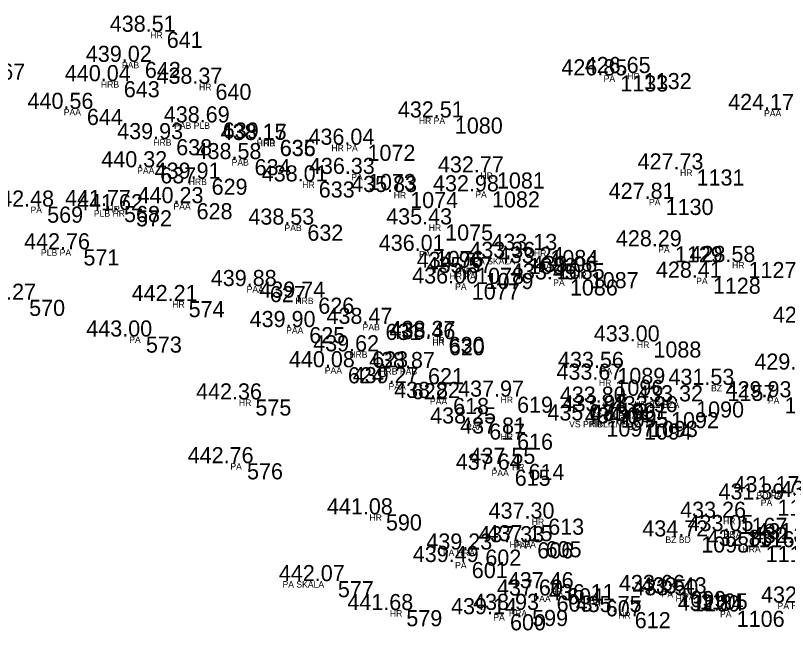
# Model space of a CAD drawing. Extents: x -639390 to -639075, y -1138747 to -1138358.
# Drawn here: x -639130.26 to -639094.29, y -1138725.69 to -1138697.05 of the extents above; entities that cross this region are included whole.
import ezdxf

# ---------------------------------------------------------------- set-up
doc = ezdxf.new("R2010")
doc.units = 0
for name, color, linetype in [('Vrstva 11', 7, 'Continuous'), ('Vrstva 12', 7, 'Continuous'), ('Vrstva 13', 7, 'Continuous'), ('Vrstva 57', 7, 'Continuous')]:
    doc.layers.add(name, color=color, linetype=linetype)

msp = doc.modelspace()

# ---------------------------------------------------------------- linework, layer by layer
at = {"layer": 'Vrstva 11'}
for p, q in [((-639123.49, -1138697.81), (-639123.49, -1138697.81)), ((-639124.51, -1138699.21), (-639124.51, -1138699.21)), ((-639102.36, -1138699.84), (-639102.36, -1138699.84)), ((-639101.27, -1138699.73), (-639101.27, -1138699.73)), ((-639125.49, -1138700.11), (-639125.49, -1138700.11)), ((-639121.22, -1138700.23), (-639121.22, -1138700.23)), ((-639127.21, -1138701.4), (-639127.21, -1138701.4)), ((-639094.59, -1138701.45), (-639094.59, -1138701.45)), ((-639110.07, -1138701.8), (-639110.07, -1138701.8)), ((-639120.88, -1138702.03), (-639120.88, -1138702.03)), ((-639123.05, -1138702.81), (-639123.05, -1138702.81)), ((-639118.23, -1138702.84), (-639118.23, -1138702.84)), ((-639118.22, -1138702.85), (-639118.22, -1138702.85)), ((-639114.14, -1138703.07), (-639114.14, -1138703.07)), ((-639119.4, -1138703.74), (-639119.4, -1138703.74)), ((-639123.79, -1138704.12), (-639123.79, -1138704.12)), ((-639108.11, -1138704.36), (-639108.11, -1138704.36)), ((-639098.81, -1138704.22), (-639098.81, -1138704.22)), ((-639121.4, -1138704.65), (-639121.4, -1138704.65)), ((-639114.12, -1138704.43), (-639114.12, -1138704.43)), ((-639116.41, -1138704.78), (-639116.41, -1138704.78)), ((-639112.15, -1138705.27), (-639112.15, -1138705.27)), ((-639108.34, -1138705.24), (-639108.34, -1138705.24)), ((-639122.1, -1138705.79), (-639122.1, -1138705.79)), ((-639100.25, -1138705.59), (-639100.25, -1138705.59)), ((-639129.06, -1138705.95), (-639129.06, -1138705.95)), ((-639125.48, -1138705.92), (-639125.48, -1138705.92)), ((-639124.92, -1138706.12), (-639124.92, -1138706.12)), ((-639116.94, -1138706.79), (-639116.94, -1138706.79)), ((-639110.52, -1138706.78), (-639110.52, -1138706.78)), ((-639127.37, -1138707.94), (-639127.37, -1138707.94)), ((-639105.62, -1138707.97), (-639105.62, -1138707.97)), ((-639099.82, -1138707.8), (-639099.82, -1138707.8)), ((-639110.96, -1138708.01), (-639110.96, -1138708.01)), ((-639106.63, -1138708.34), (-639106.63, -1138708.34)), ((-639105.32, -1138708.58), (-639105.32, -1138708.58)), ((-639096.39, -1138708.53), (-639096.39, -1138708.53)), ((-639109.08, -1138708.8), (-639109.08, -1138708.8)), ((-639108.64, -1138709.04), (-639108.64, -1138709.04)), ((-639103.74, -1138709), (-639103.74, -1138709)), ((-639104.71, -1138709.34), (-639104.71, -1138709.34)), ((-639098.05, -1138709.26), (-639098.05, -1138709.26)), ((-639118.69, -1138709.65), (-639118.69, -1138709.65)), ((-639109.28, -1138709.53), (-639109.28, -1138709.53)), ((-639129.9, -1138710.29), (-639129.9, -1138710.29)), ((-639122.47, -1138710.35), (-639122.47, -1138710.35)), ((-639116.43, -1138710.19), (-639116.43, -1138710.19)), ((-639116.85, -1138711.56), (-639116.85, -1138711.56)), ((-639113.3, -1138711.41), (-639113.3, -1138711.41)), ((-639124.46, -1138712), (-639124.46, -1138712)), ((-639110.36, -1138712.02), (-639110.36, -1138712.02)), ((-639110.35, -1138712.12), (-639110.35, -1138712.12)), ((-639100.82, -1138712.23), (-639100.82, -1138712.23)), ((-639113.92, -1138712.69), (-639113.92, -1138712.69)), ((-639115.05, -1138713.43), (-639115.05, -1138713.43)), ((-639111.32, -1138713.47), (-639111.32, -1138713.47)), ((-639102.5, -1138713.46), (-639102.5, -1138713.46)), ((-639102.59, -1138714.01), (-639102.59, -1138714.01)), ((-639112.08, -1138714.17), (-639112.08, -1138714.17)), ((-639097.37, -1138714.25), (-639097.37, -1138714.25)), ((-639107.17, -1138714.8), (-639107.17, -1138714.8)), ((-639119.36, -1138714.93), (-639119.36, -1138714.93)), ((-639110.15, -1138714.86), (-639110.15, -1138714.86)), ((-639102.4, -1138715.08), (-639102.4, -1138715.08)), ((-639098.83, -1138715.02), (-639098.83, -1138715.02)), ((-639094.71, -1138714.83), (-639094.71, -1138714.83)), ((-639102.35, -1138715.49), (-639102.35, -1138715.49)), ((-639100, -1138715.52), (-639100, -1138715.52)), ((-639108.47, -1138716.05), (-639108.47, -1138716.05)), ((-639103.01, -1138715.91), (-639103.01, -1138715.91)), ((-639101.26, -1138716.05), (-639101.26, -1138716.05)), ((-639100.98, -1138715.93), (-639100.98, -1138715.93)), ((-639107.17, -1138716.52), (-639107.17, -1138716.52)), ((-639119.75, -1138717.9), (-639119.75, -1138717.9)), ((-639106.64, -1138717.93), (-639106.64, -1138717.93)), ((-639107.28, -1138718.2), (-639107.28, -1138718.2)), ((-639094.34, -1138719.25), (-639094.34, -1138719.25)), ((-639095.04, -1138719.59), (-639095.04, -1138719.59)), ((-639113.28, -1138720.28), (-639113.28, -1138720.28)), ((-639105.72, -1138720.48), (-639105.72, -1138720.48)), ((-639096.81, -1138720.44), (-639096.81, -1138720.44)), ((-639096.48, -1138721.06), (-639096.48, -1138721.06)), ((-639106.23, -1138721.58), (-639106.23, -1138721.58)), ((-639105.84, -1138721.53), (-639105.84, -1138721.53)), ((-639098.59, -1138721.31), (-639098.59, -1138721.31)), ((-639108.65, -1138721.92), (-639108.65, -1138721.92)), ((-639095.59, -1138721.75), (-639095.59, -1138721.75)), ((-639109.28, -1138722.5), (-639109.28, -1138722.5)), ((-639115.52, -1138723.39), (-639115.52, -1138723.39)), ((-639104.84, -1138723.72), (-639104.84, -1138723.72)), ((-639105.33, -1138724.06), (-639105.33, -1138724.06)), ((-639099.66, -1138723.85), (-639099.66, -1138723.85)), ((-639099.02, -1138724.05), (-639099.02, -1138724.05)), ((-639098.66, -1138723.96), (-639098.66, -1138723.96)), ((-639103.04, -1138724.28), (-639103.04, -1138724.28)), ((-639112.33, -1138724.74), (-639112.33, -1138724.74)), ((-639106.47, -1138724.73), (-639106.47, -1138724.73)), ((-639101.69, -1138724.83), (-639101.69, -1138724.83)), ((-639096.94, -1138724.77), (-639096.94, -1138724.77)), ((-639107.5, -1138724.93), (-639107.5, -1138724.93))]:
    msp.add_line(p, q, dxfattribs=at)

# ---------------------------------------------------------------- texts
at = {"layer": 'Vrstva 12'}
for s, p in [('438.51 ', (-639125.865, -1138697.81)), ('439.02 ', (-639126.979, -1138699.21)), ('426.65 ', (-639103.74, -1138699.73)), ('426.85 ', (-639104.83, -1138699.84)), ('440.04 ', (-639127.959, -1138700.11)), ('438.37 ', (-639123.689, -1138700.23)), ('440.56 ', (-639129.696, -1138701.4)), ('424.17 ', (-639097.059, -1138701.45)), ('432.51 ', (-639112.445, -1138701.8)), ('438.69 ', (-639123.349, -1138702.03)), ('439.93 ', (-639125.519, -1138702.81)), ('438.15 ', (-639120.7, -1138702.84)), ('438.17 ', (-639120.689, -1138702.85)), ('436.04 ', (-639116.609, -1138703.07)), ('438.58 ', (-639121.869, -1138703.74)), ('440.32 ', (-639126.259, -1138704.12)), ('432.77 ', (-639110.579, -1138704.36)), ('427.73 ', (-639101.279, -1138704.22)), ('439.91 ', (-639123.775, -1138704.65)), ('438.01 ', (-639118.785, -1138704.78)), ('436.33 ', (-639116.589, -1138704.43)), ('435.83 ', (-639114.619, -1138705.27)), ('432.98 ', (-639110.809, -1138705.24)), ('440.23 ', (-639124.569, -1138705.79)), ('427.81 ', (-639102.625, -1138705.59)), ('442.48 ', (-639131.529, -1138705.95)), ('441.77 ', (-639127.949, -1138705.92)), ('441.62 ', (-639127.389, -1138706.12)), ('438.53 ', (-639119.409, -1138706.79)), ('435.43 ', (-639112.989, -1138706.78)), ('442.76 ', (-639129.856, -1138707.94)), ('436.01 ', (-639113.335, -1138708.01)), ('433.13 ', (-639108.089, -1138707.97)), ('428.29 ', (-639102.289, -1138707.8)), ('433.36 ', (-639109.116, -1138708.34)), ('433.24 ', (-639107.789, -1138708.58)), ('428.58 ', (-639098.859, -1138708.53)), ('434.96 ', (-639111.566, -1138708.8)), ('435.57 ', (-639111.109, -1138709.04)), ('433.06 ', (-639106.226, -1138709)), ('433.45 ', (-639107.18, -1138709.34)), ('428.41 ', (-639100.425, -1138709.26)), ('439.88 ', (-639121.159, -1138709.65)), ('436.00 ', (-639111.779, -1138709.53)), ('445.27 ', (-639132.369, -1138710.29)), ('442.21 ', (-639124.845, -1138710.35)), ('439.74 ', (-639118.899, -1138710.19)), ('439.90 ', (-639119.349, -1138711.56)), ('438.47 ', (-639115.769, -1138711.41)), ('427.94 ', (-639094.979, -1138711.36)), ('443.00 ', (-639126.959, -1138712)), ('438.46 ', (-639112.836, -1138712.12)), ('438.37 ', (-639112.829, -1138712.02)), ('433.00 ', (-639103.319, -1138712.23)), ('439.62 ', (-639116.389, -1138712.69)), ('440.08 ', (-639117.519, -1138713.43)), ('438.87 ', (-639113.789, -1138713.47)), ('433.56 ', (-639104.986, -1138713.46)), ('429.50 ', (-639095.839, -1138713.54)), ('433.67 ', (-639105.059, -1138714.01)), ('439.27 ', (-639114.549, -1138714.17)), ('431.53 ', (-639099.839, -1138714.25)), ('437.97 ', (-639109.639, -1138714.8)), ('429.93 ', (-639097.179, -1138714.83)), ('442.36 ', (-639121.846, -1138714.93)), ('438.82 ', (-639112.619, -1138714.86)), ('433.80 ', (-639104.899, -1138715.08)), ('433.32 ', (-639101.299, -1138715.02)), ('433.98 ', (-639104.819, -1138715.49)), ('433.96 ', (-639102.486, -1138715.52)), ('435.07 ', (-639105.479, -1138715.91)), ('433.96 ', (-639103.466, -1138715.93)), ('438.25 ', (-639110.94, -1138716.05)), ('434.04 ', (-639103.729, -1138716.05)), ('437.81 ', (-639109.545, -1138716.52)), ('442.76 ', (-639122.236, -1138717.9)), ('437.55 ', (-639109.11, -1138717.93)), ('437.64 ', (-639109.749, -1138718.2)), ('431.17 ', (-639096.809, -1138719.25)), ('431.23 ', (-639094.629, -1138719.47)), ('431.39 ', (-639097.509, -1138719.59)), ('441.08 ', (-639115.749, -1138720.28)), ('437.30 ', (-639108.219, -1138720.48)), ('433.26 ', (-639099.296, -1138720.44)), ('434.72 ', (-639101.059, -1138721.31)), ('433.05 ', (-639098.95, -1138721.06)), ('437.33 ', (-639108.699, -1138721.58)), ('437.15 ', (-639108.31, -1138721.53)), ('432.38 ', (-639095.959, -1138721.62)), ('431.79 ', (-639095.749, -1138721.44)), ('439.23 ', (-639111.119, -1138721.92)), ('432.83 ', (-639098.059, -1138721.75)), ('439.49 ', (-639111.749, -1138722.5)), ('442.07 ', (-639117.989, -1138723.39)), ('437.46 ', (-639107.326, -1138723.72)), ('437.60 ', (-639107.829, -1138724.06)), ('433.66 ', (-639102.146, -1138723.85)), ('433.50 ', (-639101.519, -1138724.05)), ('433.43 ', (-639101.129, -1138723.96)), ('436.11 ', (-639105.415, -1138724.28)), ('432.47 ', (-639095.529, -1138724.39)), ('441.68 ', (-639114.799, -1138724.74)), ('438.93 ', (-639108.939, -1138724.73)), ('435.75 ', (-639104.16, -1138724.83)), ('432.84 ', (-639099.409, -1138724.77)), ('439.14 ', (-639109.969, -1138724.93))]:
    msp.add_text(s, height=0.75, dxfattribs=at).set_placement(p)
at = {"layer": 'Vrstva 13'}
for s, p in [(' 641', (-639123.49, -1138698.56)), (' 567', (-639131.76, -1138700.04)), (' 642', (-639124.51, -1138699.96)), (' 1133', (-639102.36, -1138700.59)), (' 1132', (-639101.27, -1138700.48)), (' 643', (-639125.49, -1138700.86)), (' 640', (-639121.22, -1138700.98)), (' 644', (-639127.21, -1138702.15)), (' 1080', (-639110.07, -1138702.55)), (' 639', (-639120.88, -1138702.78)), (' 638', (-639123.05, -1138703.56)), (' 635', (-639118.23, -1138703.59)), (' 636', (-639118.22, -1138703.6)), (' 1072', (-639114.14, -1138703.82)), (' 634', (-639119.4, -1138704.49)), (' 637', (-639123.79, -1138704.87)), (' 1081', (-639108.11, -1138705.11)), (' 1131', (-639098.81, -1138704.97)), (' 629', (-639121.4, -1138705.4)), (' 1073', (-639114.12, -1138705.18)), (' 633', (-639116.41, -1138705.53)), (' 1074', (-639112.15, -1138706.02)), (' 1082', (-639108.34, -1138705.99)), (' 628', (-639122.1, -1138706.54)), (' 1130', (-639100.25, -1138706.34)), (' 569', (-639129.06, -1138706.7)), (' 568', (-639125.48, -1138706.67)), (' 572', (-639124.92, -1138706.87)), (' 632', (-639116.94, -1138707.54)), (' 1075', (-639110.52, -1138707.53)), (' 571', (-639127.37, -1138708.69)), (' 1084', (-639105.62, -1138708.72)), (' 1129', (-639099.82, -1138708.55)), (' 1076', (-639110.96, -1138708.76)), (' 1083', (-639106.63, -1138709.09)), (' 1085', (-639105.32, -1138709.33)), (' 1127', (-639096.39, -1138709.28)), (' 1078', (-639109.08, -1138709.55)), (' 1079', (-639108.64, -1138709.79)), (' 1087', (-639103.74, -1138709.75)), (' 1086', (-639104.71, -1138710.09)), (' 1128', (-639098.05, -1138710.01)), (' 627', (-639118.69, -1138710.4)), (' 1077', (-639109.28, -1138710.28)), (' 570', (-639129.9, -1138711.04)), (' 574', (-639122.47, -1138711.1)), (' 626', (-639116.43, -1138710.94)), (' 625', (-639116.85, -1138712.31)), (' 631', (-639113.3, -1138712.16)), (' 573', (-639124.46, -1138712.75)), (' 630', (-639110.36, -1138712.77)), (' 620', (-639110.35, -1138712.87)), (' 1088', (-639100.82, -1138712.98)), (' 623', (-639113.92, -1138713.44)), (' 624', (-639115.05, -1138714.18)), (' 621', (-639111.32, -1138714.22)), (' 1089', (-639102.5, -1138714.21)), (' 1096', (-639102.59, -1138714.76)), (' 622', (-639112.08, -1138714.92)), (' 1157', (-639097.37, -1138715)), (' 619', (-639107.17, -1138715.55)), (' 575', (-639119.36, -1138715.68)), (' 618', (-639110.15, -1138715.61)), (' 1091', (-639102.4, -1138715.83)), (' 1090', (-639098.83, -1138715.77)), (' 1125', (-639094.71, -1138715.58)), (' 1095', (-639102.35, -1138716.24)), (' 1092', (-639100, -1138716.27)), (' 617', (-639108.47, -1138716.8)), (' 1097', (-639103.01, -1138716.66)), (' 1094', (-639101.26, -1138716.8)), (' 1093', (-639100.98, -1138716.68)), (' 616', (-639107.17, -1138717.27)), (' 576', (-639119.75, -1138718.65)), (' 614', (-639106.64, -1138718.68)), (' 615', (-639107.28, -1138718.95)), (' 1117', (-639095.04, -1138720.34)), (' 590', (-639113.28, -1138721.03)), (' 613', (-639105.72, -1138721.23)), (' 1167', (-639096.81, -1138721.19)), (' 1116', (-639096.48, -1138721.81)), (' 606', (-639106.23, -1138722.33)), (' 605', (-639105.84, -1138722.28)), (' 1098', (-639098.59, -1138722.06)), (' 602', (-639108.65, -1138722.67)), (' 1115', (-639095.59, -1138722.5)), (' 601', (-639109.28, -1138723.25)), (' 577', (-639115.52, -1138724.14)), (' 604', (-639104.84, -1138724.47)), (' 603', (-639105.33, -1138724.81)), (' 1099', (-639099.66, -1138724.6)), (' 1100', (-639099.02, -1138724.8)), (' 1105', (-639098.66, -1138724.71)), (' 607', (-639103.04, -1138725.03)), (' 579', (-639112.33, -1138725.49)), (' 599', (-639106.47, -1138725.48)), (' 612', (-639101.69, -1138725.58)), (' 1106', (-639096.94, -1138725.52)), (' 600', (-639107.5, -1138725.68))]:
    msp.add_text(s, height=0.75, dxfattribs=at).set_placement(p)
at = {"layer": 'Vrstva 57'}
for s, p in [('HR', (-639123.979, -1138698.11)), ('PAB', (-639125.299, -1138699.51)), ('PA', (-639102.86, -1138700.14)), ('HR', (-639101.759, -1138700.03)), ('HRB', (-639126.279, -1138700.41)), ('HR', (-639121.709, -1138700.53)), ('PAA', (-639128.01, -1138701.7)), ('PAA', (-639095.39, -1138701.75)), ('HR PA', (-639111.47, -1138702.1)), ('PAB PLB', (-639122.869, -1138702.33)), ('HRB', (-639123.839, -1138703.11)), ('HRB', (-639119.019, -1138703.14)), ('HR', (-639118.709, -1138703.15)), ('HR PA', (-639115.54, -1138703.37)), ('PAB', (-639120.189, -1138704.04)), ('PAA', (-639124.59, -1138704.42)), ('HR', (-639108.599, -1138704.66)), ('HR', (-639099.299, -1138704.52)), ('HRB', (-639122.189, -1138704.95)), ('PA', (-639114.62, -1138704.73)), ('HR', (-639116.899, -1138705.08)), ('HR', (-639112.639, -1138705.57)), ('PA', (-639108.84, -1138705.54)), ('PAA', (-639122.9, -1138706.09)), ('PA', (-639100.75, -1138705.89)), ('PA', (-639129.56, -1138706.25)), ('PLB HR', (-639126.609, -1138706.42)), ('HR', (-639125.969, -1138706.22)), ('PAB', (-639117.729, -1138707.09)), ('HR', (-639111.009, -1138707.08)), ('PLB PA', (-639129.07, -1138708.24)), ('HR', (-639106.109, -1138708.27)), ('PA', (-639100.32, -1138708.1)), ('PA', (-639111.46, -1138708.31)), ('PA SKALA', (-639108.93, -1138708.64)), ('PA', (-639105.82, -1138708.88)), ('HR', (-639096.879, -1138708.83)), ('HR PA', (-639110.04, -1138709.34)), ('HR', (-639109.569, -1138709.1)), ('HR', (-639104.229, -1138709.3)), ('PA', (-639105.21, -1138709.64)), ('PA', (-639098.55, -1138709.56)), ('PAA', (-639119.49, -1138709.95)), ('PA', (-639109.78, -1138709.83)), ('HR', (-639122.959, -1138710.65)), ('HRB', (-639117.219, -1138710.49)), ('PAA', (-639117.65, -1138711.86)), ('PAB', (-639114.089, -1138711.71)), ('PA', (-639124.96, -1138712.3)), ('HR', (-639110.849, -1138712.32)), ('HR', (-639110.839, -1138712.42)), ('HR', (-639101.309, -1138712.53)), ('HRB', (-639114.709, -1138712.99)), ('PAA', (-639115.85, -1138713.73)), ('HRB PAB', (-639113.309, -1138713.77)), ('PA', (-639103, -1138713.76)), ('HR', (-639103.079, -1138714.31)), ('PAA', (-639112.88, -1138714.47)), ('BZ', (-639097.859, -1138714.55)), ('HR', (-639107.659, -1138715.1)), ('HR', (-639119.849, -1138715.23)), ('PAA', (-639110.95, -1138715.16)), ('PA', (-639102.9, -1138715.38)), ('HR BZ BZA', (-639101.43, -1138715.32)), ('PA', (-639095.21, -1138715.13)), ('VS PRIBLIZNE', (-639103.488, -1138715.82)), ('PA', (-639102.85, -1138715.79)), ('PAA', (-639109.27, -1138716.35)), ('VS PRIBLIZNE', (-639104.468, -1138716.23)), ('HR', (-639103.499, -1138716.21)), ('BZ', (-639101.749, -1138716.35)), ('HR', (-639107.659, -1138716.82)), ('PA', (-639120.25, -1138718.2)), ('HR', (-639107.129, -1138718.23)), ('PAA', (-639108.08, -1138718.5)), ('BD PA', (-639095.74, -1138719.55)), ('PA', (-639095.54, -1138719.89)), ('HR', (-639113.769, -1138720.58)), ('HR', (-639106.209, -1138720.78)), ('HR', (-639097.299, -1138720.74)), ('HRA', (-639097.28, -1138721.36)), ('HR PA', (-639107.24, -1138721.83)), ('PAA', (-639107.03, -1138721.88)), ('BZ BD', (-639099.981, -1138721.61)), ('PA HRA', (-639110.35, -1138722.22)), ('HRA', (-639096.39, -1138722.05)), ('PA', (-639109.78, -1138722.8)), ('PA SKALA', (-639117.82, -1138723.69)), ('HR', (-639105.329, -1138724.02)), ('PAA', (-639106.13, -1138724.36)), ('PA', (-639100.16, -1138724.15)), ('HR', (-639099.509, -1138724.35)), ('PA', (-639099.16, -1138724.26)), ('PA', (-639103.54, -1138724.58)), ('PA HRA', (-639094.76, -1138724.69)), ('HR', (-639112.819, -1138725.04)), ('HRA', (-639107.27, -1138725.03)), ('HR', (-639102.179, -1138725.13)), ('PA', (-639097.44, -1138725.07)), ('PA', (-639108, -1138725.23))]:
    msp.add_text(s, height=0.3, dxfattribs=at).set_placement(p)

doc.saveas('drawing.dxf')
